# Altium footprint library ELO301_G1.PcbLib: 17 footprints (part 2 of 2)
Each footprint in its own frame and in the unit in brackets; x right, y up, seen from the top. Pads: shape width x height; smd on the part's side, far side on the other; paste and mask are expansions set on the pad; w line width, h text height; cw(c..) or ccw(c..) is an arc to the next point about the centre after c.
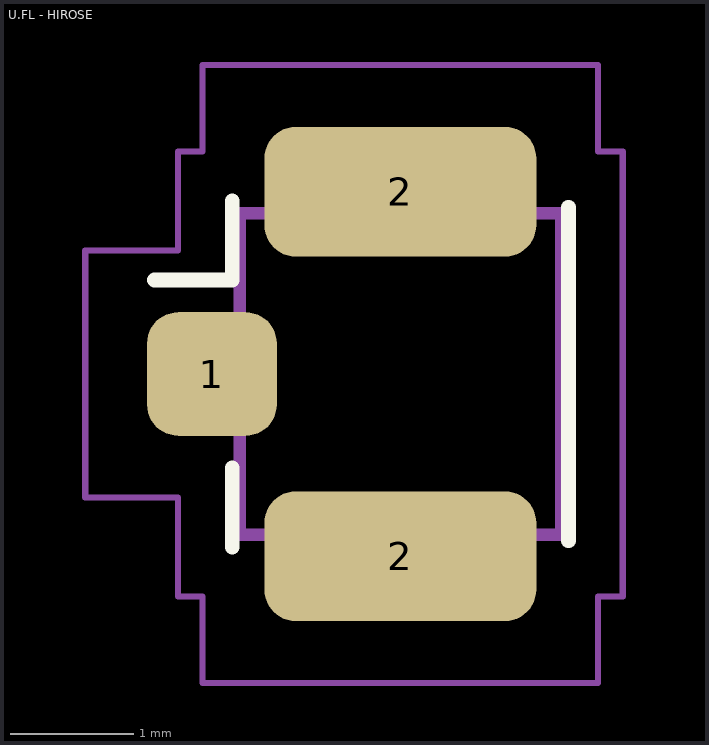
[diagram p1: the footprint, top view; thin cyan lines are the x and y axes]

## U.FL - HIROSE [mm] "Hirose U.FL Coaxial (https://www.hirose.com/en/product/document?clcode=CL0331-0472-2-01&productname=U.FL-R-SMT-1(01)&series=U.FL&documenttype=2DDrawing&lang=en&documentid=0000940668)"
pads (3):
  rrect50% 1.05x1 smd: 1(1268.475,1270)
  rrect48% 2.2x1.05 smd: 2(1270,1268.525) 2(1270,1271.475)
Top Overlay:
  lines w0.12: 1268.01,1270.76 1268.64,1270.76 1268.64,1271.4 ; 1268.64,1268.6 1268.64,1269.24 ; 1271.36,1268.65 1271.36,1271.35
Mechanical 13:
  lines w0.1: 1268.45,1269.7 1268.45,1270.15 1268.6,1270.3 1268.7,1270.3 1268.7,1271.3 1269.1,1271.3 1269.1,1271.5 1270.9,1271.5 1270.9,1271.3 1271.3,1271.3 1271.3,1268.7 1270.9,1268.7 1270.9,1268.5 1269.1,1268.5 1269.1,1268.7 1268.7,1268.7 1268.7,1269.7 1268.45,1269.7
Mechanical 15:
  lines w0.05: 1267.45,1269 1268.2,1269 1268.2,1268.2 1268.4,1268.2 1268.4,1267.5 1271.6,1267.5 1271.6,1268.2 1271.8,1268.2 1271.8,1271.8 1271.6,1271.8 1271.6,1272.5 1268.4,1272.5 1268.4,1271.8 1268.2,1271.8 1268.2,1271 1267.45,1271 1267.45,1269
Mechanical 29:
  text ".Designator" at 1269.492,1269.898 h0.25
